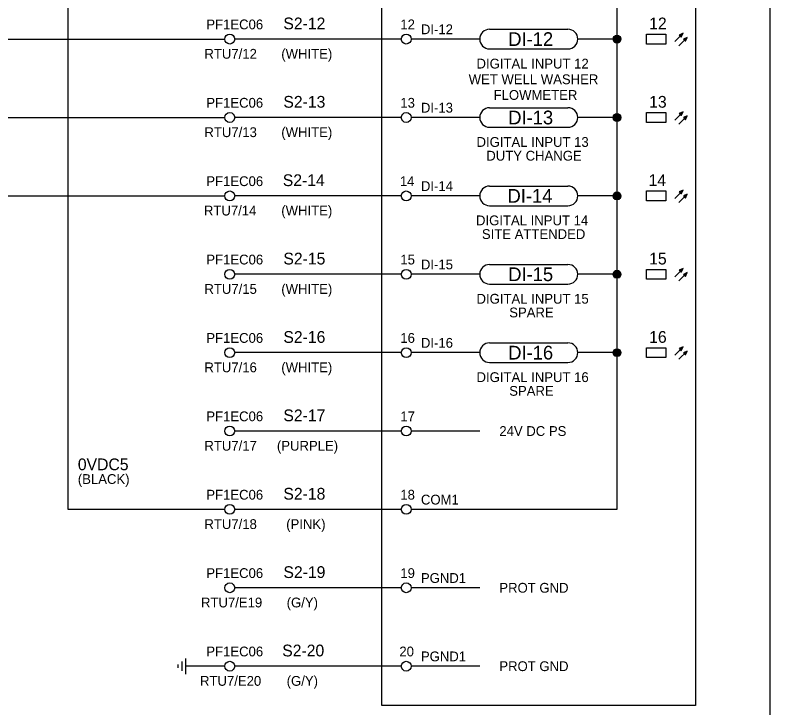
# Model space of a CAD drawing. Extents: x 0 to 841, y 0 to 594.
# Drawn here: x 636.5 to 829, y 89.4 to 266.1 of the extents above; entities that cross this region are included whole.
import ezdxf

# ---------------------------------------------------------------- set-up
doc = ezdxf.new("R2010")
doc.units = 0
for name, color, linetype in [('A1BORDER', 7, 'Continuous'), ('Default', 7, 'Continuous'), ('Level 1', 7, 'Continuous'), ('Level 10', 7, 'Continuous')]:
    doc.layers.add(name, color=color, linetype=linetype)

msp = doc.modelspace()

# ---------------------------------------------------------------- linework, layer by layer
at = {"layer": 'A1BORDER'}
msp.add_line((829, 581), (829, 15), dxfattribs=at)
at = {"layer": 'Default'}
msp.add_line((650, 140), (650, 520), dxfattribs=at)
at = {"layer": 'Level 1'}
for p, q in [((790, 480), (790, 140)), ((757.5, 262.5), (777.5, 262.5)), ((272.5, 260), (690, 260)), ((735, 260), (692.5, 260)), ((755, 260), (737.5, 260)), ((790, 260), (780, 260)), ((757.5, 257.5), (777.5, 257.5)), ((757.5, 242.5), (777.5, 242.5)), ((355, 240), (690, 240)), ((735, 240), (692.5, 240)), ((755, 240), (737.5, 240)), ((790, 240), (780, 240)), ((757.5, 237.5), (777.5, 237.5)), ((757.5, 222.5), (777.5, 222.5)), ((475, 220), (690, 220)), ((735, 220), (692.5, 220)), ((755, 220), (737.5, 220)), ((790, 220), (780, 220)), ((757.5, 217.5), (777.5, 217.5)), ((757.5, 202.5), (777.5, 202.5)), ((735, 200), (692.5, 200)), ((755, 200), (737.5, 200)), ((790, 200), (780, 200)), ((757.5, 197.5), (777.5, 197.5)), ((757.5, 182.5), (777.5, 182.5)), ((735, 180), (692.5, 180)), ((755, 180), (737.5, 180)), ((790, 180), (780, 180)), ((757.5, 177.5), (777.5, 177.5)), ((735, 160), (692.5, 160)), ((755, 160), (737.5, 160)), ((690, 140), (650, 140)), ((735, 140), (692.5, 140)), ((790, 140), (737.5, 140)), ((735, 120), (692.5, 120)), ((755, 120), (737.5, 120)), ((690, 100), (680, 100)), ((735, 100), (692.5, 100)), ((755, 100), (737.5, 100))]:
    msp.add_line(p, q, dxfattribs=at)
for points in [[(730, 540), (810, 540), (810, 90), (730, 90)], [(797.5, 261.25), (802.5, 261.25), (802.5, 258.75), (797.5, 258.75)], [(797.5, 241.25), (802.5, 241.25), (802.5, 238.75), (797.5, 238.75)], [(797.5, 221.25), (802.5, 221.25), (802.5, 218.75), (797.5, 218.75)], [(797.5, 201.25), (802.5, 201.25), (802.5, 198.75), (797.5, 198.75)], [(797.5, 181.25), (802.5, 181.25), (802.5, 178.75), (797.5, 178.75)]]:
    msp.add_lwpolyline(points, close=True, dxfattribs=at)
for centre, start, end in [((757.5, 260), 90, 270), ((777.5, 260), 270, 90), ((757.5, 240), 90, 270), ((777.5, 240), 270, 90), ((757.5, 220), 90, 270), ((777.5, 220), 270, 90), ((757.5, 200), 90, 270), ((777.5, 200), 270, 90), ((757.5, 180), 90, 270), ((777.5, 180), 270, 90)]:
    msp.add_arc(centre, 2.5, start, end, dxfattribs=at)
at = {"layer": 'Level 10'}
for p, q in [((789.01, 260.1), (790.99, 260.1)), ((789.08, 260.4), (790.92, 260.4)), ((789.29, 260.7), (790.71, 260.7)), ((790, 261), (790, 261)), ((804.73, 259.36), (806.86, 261.48)), ((805.79, 258.3), (807.91, 260.42)), ((805.96, 261.07), (806.67, 261.07)), ((806, 260.93), (806.61, 260.93)), ((806.14, 260.77), (806.53, 260.77)), ((806.29, 261.23), (806.74, 261.23)), ((806.3, 260.62), (806.47, 260.62)), ((806.62, 261.38), (806.81, 261.38)), ((807.02, 260.01), (807.73, 260.01)), ((807.35, 260.17), (807.8, 260.17)), ((807.68, 260.31), (807.87, 260.31)), ((789.02, 259.8), (790.98, 259.8)), ((789.13, 259.5), (790.87, 259.5)), ((789.4, 259.2), (790.6, 259.2)), ((807.06, 259.87), (807.66, 259.87)), ((807.21, 259.72), (807.6, 259.72)), ((807.36, 259.56), (807.53, 259.56)), ((789.29, 240.7), (790.71, 240.7)), ((790, 241), (790, 241)), ((804.73, 239.36), (806.86, 241.48)), ((805.96, 241.08), (806.67, 241.08)), ((806, 240.93), (806.61, 240.93)), ((806.14, 240.78), (806.53, 240.78)), ((806.29, 241.22), (806.74, 241.22)), ((806.3, 240.62), (806.47, 240.62)), ((806.62, 241.38), (806.81, 241.38)), ((789.01, 240.1), (790.99, 240.1)), ((789.02, 239.8), (790.98, 239.8)), ((789.08, 240.4), (790.92, 240.4)), ((789.13, 239.5), (790.87, 239.5)), ((789.4, 239.2), (790.6, 239.2)), ((805.79, 238.3), (807.91, 240.42)), ((807.02, 240.02), (807.73, 240.02)), ((807.06, 239.87), (807.66, 239.87)), ((807.21, 239.72), (807.6, 239.72)), ((807.35, 240.16), (807.8, 240.16)), ((807.36, 239.56), (807.53, 239.56)), ((807.68, 240.31), (807.87, 240.31)), ((804.73, 219.36), (806.86, 221.48)), ((806.62, 221.38), (806.81, 221.38)), ((789.01, 220.1), (790.99, 220.1)), ((789.02, 219.8), (790.98, 219.8)), ((789.08, 220.4), (790.92, 220.4)), ((789.13, 219.5), (790.87, 219.5)), ((789.29, 220.7), (790.71, 220.7)), ((790, 221), (790, 221)), ((805.79, 218.3), (807.91, 220.42)), ((805.96, 221.08), (806.67, 221.08)), ((806, 220.93), (806.61, 220.93)), ((806.14, 220.78), (806.53, 220.78)), ((806.29, 221.22), (806.74, 221.22)), ((806.3, 220.62), (806.47, 220.62)), ((807.02, 220.02), (807.73, 220.02)), ((807.06, 219.87), (807.66, 219.87)), ((807.21, 219.72), (807.6, 219.72)), ((807.35, 220.16), (807.8, 220.16)), ((807.36, 219.56), (807.53, 219.56)), ((807.68, 220.31), (807.87, 220.31)), ((789.4, 219.2), (790.6, 219.2)), ((789.08, 200.4), (790.92, 200.4)), ((789.29, 200.7), (790.71, 200.7)), ((790, 201), (790, 201)), ((804.73, 199.36), (806.86, 201.48)), ((805.79, 198.3), (807.91, 200.42)), ((805.96, 201.08), (806.67, 201.08)), ((806, 200.93), (806.61, 200.93)), ((806.14, 200.78), (806.53, 200.78)), ((806.29, 201.22), (806.74, 201.22)), ((806.3, 200.62), (806.47, 200.62)), ((806.62, 201.38), (806.81, 201.38)), ((807.68, 200.31), (807.87, 200.31)), ((789.01, 200.1), (790.99, 200.1)), ((789.02, 199.8), (790.98, 199.8)), ((789.13, 199.5), (790.87, 199.5)), ((789.4, 199.2), (790.6, 199.2)), ((807.02, 200.02), (807.73, 200.02)), ((807.06, 199.87), (807.66, 199.87)), ((807.21, 199.72), (807.6, 199.72)), ((807.35, 200.16), (807.8, 200.16)), ((807.36, 199.56), (807.53, 199.56)), ((790, 181), (790, 181)), ((804.73, 179.35), (806.86, 181.48)), ((805.96, 181.08), (806.67, 181.08)), ((806.29, 181.22), (806.74, 181.22)), ((806.62, 181.38), (806.81, 181.38)), ((789.01, 180.1), (790.99, 180.1)), ((789.02, 179.8), (790.98, 179.8)), ((789.08, 180.4), (790.92, 180.4)), ((789.13, 179.5), (790.87, 179.5)), ((789.29, 180.7), (790.71, 180.7)), ((789.4, 179.2), (790.6, 179.2)), ((805.79, 178.3), (807.91, 180.42)), ((806, 180.93), (806.61, 180.93)), ((806.14, 180.78), (806.53, 180.78)), ((806.3, 180.62), (806.47, 180.62)), ((807.02, 180.02), (807.73, 180.02)), ((807.06, 179.87), (807.66, 179.87)), ((807.21, 179.72), (807.6, 179.72)), ((807.35, 180.16), (807.8, 180.16)), ((807.36, 179.56), (807.53, 179.56)), ((807.68, 180.31), (807.87, 180.31)), ((678, 100.4), (678, 99.6)), ((679, 101.2), (679, 98.8)), ((680, 102), (680, 98))]:
    msp.add_line(p, q, dxfattribs=at)
for points in [[(806.86, 261.48), (805.88, 261.04), (806.41, 260.5)], [(807.91, 260.42), (806.94, 259.98), (807.48, 259.44)], [(806.86, 241.48), (805.88, 241.04), (806.41, 240.5)], [(807.91, 240.42), (806.94, 239.98), (807.48, 239.44)], [(806.86, 221.48), (805.88, 221.04), (806.41, 220.5)], [(807.91, 220.42), (806.94, 219.98), (807.48, 219.44)], [(806.86, 201.48), (805.88, 201.04), (806.41, 200.5)], [(807.91, 200.42), (806.94, 199.98), (807.48, 199.44)], [(806.86, 181.48), (805.88, 181.04), (806.41, 180.5)], [(807.91, 180.42), (806.94, 179.98), (807.48, 179.44)]]:
    msp.add_lwpolyline(points, close=True, dxfattribs=at)
for centre, radius in [((691.25, 260), 1.25), ((736.25, 260), 1.25), ((790, 260), 1), ((691.25, 240), 1.25), ((736.25, 240), 1.25), ((790, 240), 1), ((691.25, 220), 1.25), ((736.25, 220), 1.25), ((790, 220), 1), ((691.25, 200), 1.25), ((736.25, 200), 1.25), ((790, 200), 1), ((691.25, 180), 1.25), ((736.25, 180), 1.25), ((790, 180), 1), ((691.25, 160), 1.25), ((736.25, 160), 1.25), ((691.25, 140), 1.25), ((736.25, 140), 1.25), ((691.25, 120), 1.25), ((736.25, 120), 1.25), ((691.25, 100), 1.25), ((736.25, 100), 1.25)]:
    msp.add_circle(centre, radius, dxfattribs=at)

# ---------------------------------------------------------------- texts
at = {"layer": 'Level 1'}
for s, height, p in [('PF1EC06', 2.5, (685.27, 262.5)), ('S2-12', 3, (704.92, 262.5)), ('12', 2.5, (734.75, 262.5)), ('DI-12', 2.5, (740, 261.25)), ('12', 3, (798.21, 262.5)), ('DI-12', 3.5, (762.27, 258.25)), ('RTU7/12', 2.5, (684.78, 255)), ('(WHITE)', 2.5, (704.39, 255)), ('DIGITAL INPUT 12', 2.5, (754.18, 252.5)), ('WET WELL WASHER', 2.5, (752.18, 248.5)), ('FLOWMETER', 2.5, (758.54, 244.5)), ('PF1EC06', 2.5, (685.27, 242.5)), ('S2-13', 3, (704.92, 242.5)), ('13', 2.5, (734.75, 242.5)), ('13', 3, (798.21, 242.5)), ('DI-13', 2.5, (740, 241.25)), ('DI-13', 3.5, (762.27, 238.25)), ('RTU7/13', 2.5, (684.78, 235)), ('(WHITE)', 2.5, (704.39, 235)), ('DIGITAL INPUT 13', 2.5, (754.18, 232.5)), ('DUTY CHANGE', 2.5, (756.67, 229)), ('S2-14', 3, (704.77, 222.5)), ('14', 3, (798.06, 222.5)), ('PF1EC06', 2.5, (685.27, 222.5)), ('14', 2.5, (734.63, 222.5)), ('DI-14', 2.5, (740, 221.25)), ('DI-14', 3.5, (762.09, 218.25)), ('RTU7/14', 2.5, (684.66, 215)), ('(WHITE)', 2.5, (704.39, 215)), ('DIGITAL INPUT 14', 2.5, (754.05, 212.5)), ('SITE ATTENDED', 2.5, (755.55, 209)), ('PF1EC06', 2.5, (685.27, 202.5)), ('S2-15', 3, (704.92, 202.5)), ('15', 2.5, (734.75, 202.5)), ('15', 3, (798.21, 202.5)), ('DI-15', 2.5, (740, 201.25)), ('DI-15', 3.5, (762.27, 198.25)), ('RTU7/15', 2.5, (684.78, 195)), ('(WHITE)', 2.5, (704.39, 195)), ('DIGITAL INPUT 15', 2.5, (754.18, 192.5)), ('SPARE', 2.5, (762.52, 189)), ('PF1EC06', 2.5, (685.27, 182.5)), ('S2-16', 3, (704.92, 182.5)), ('16', 2.5, (734.75, 182.5)), ('16', 3, (798.21, 182.5)), ('DI-16', 2.5, (740, 181.25)), ('DI-16', 3.5, (762.27, 178.25)), ('RTU7/16', 2.5, (684.78, 175)), ('(WHITE)', 2.5, (704.39, 175)), ('DIGITAL INPUT 16', 2.5, (754.18, 172.5)), ('SPARE', 2.5, (762.52, 169)), ('PF1EC06', 2.5, (685.27, 162.5)), ('S2-17', 3, (704.92, 162.5)), ('17', 2.5, (734.75, 162.5)), ('24V DC PS', 2.5, (760, 158.75)), ('RTU7/17', 2.5, (684.78, 155)), ('(PURPLE)', 2.5, (703.27, 155)), ('0VDC5', 3, (652.5, 150)), ('(BLACK)', 2.5, (652.5, 146.5)), ('PF1EC06', 2.5, (685.27, 142.5)), ('S2-18', 3, (704.92, 142.5)), ('18', 2.5, (734.75, 142.5)), ('COM1', 2.5, (740, 141.25)), ('RTU7/18', 2.5, (684.78, 135)), ('(PINK)', 2.5, (705.64, 135)), ('S2-19', 3, (704.93, 122.5)), ('PF1EC06', 2.5, (685.27, 122.5)), ('19', 2.5, (734.75, 122.5)), ('PGND1', 2.5, (740, 121.25)), ('PROT GND', 2.5, (760, 118.75)), ('RTU7/E19', 2.5, (683.91, 115)), ('(G/Y)', 2.5, (705.76, 115)), ('PF1EC06', 2.5, (685.27, 102.5)), ('S2-20', 3, (704.63, 102.5)), ('20', 2.5, (734.5, 102.5)), ('PGND1', 2.5, (740, 101.25)), ('PROT GND', 2.5, (760, 98.75)), ('RTU7/E20', 2.5, (683.66, 95)), ('(G/Y)', 2.5, (705.76, 95))]:
    msp.add_text(s, height=height, dxfattribs=at).set_placement(p)

doc.saveas('drawing.dxf')
